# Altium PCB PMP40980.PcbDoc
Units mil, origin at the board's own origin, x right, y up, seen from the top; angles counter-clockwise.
Board outline 2165.35 x 1771.65 mil, 2 copper layers (Top Layer, Bottom Layer), stack 62 mil thick; 58 components, 31 nets, 133 pads, 24 vias.
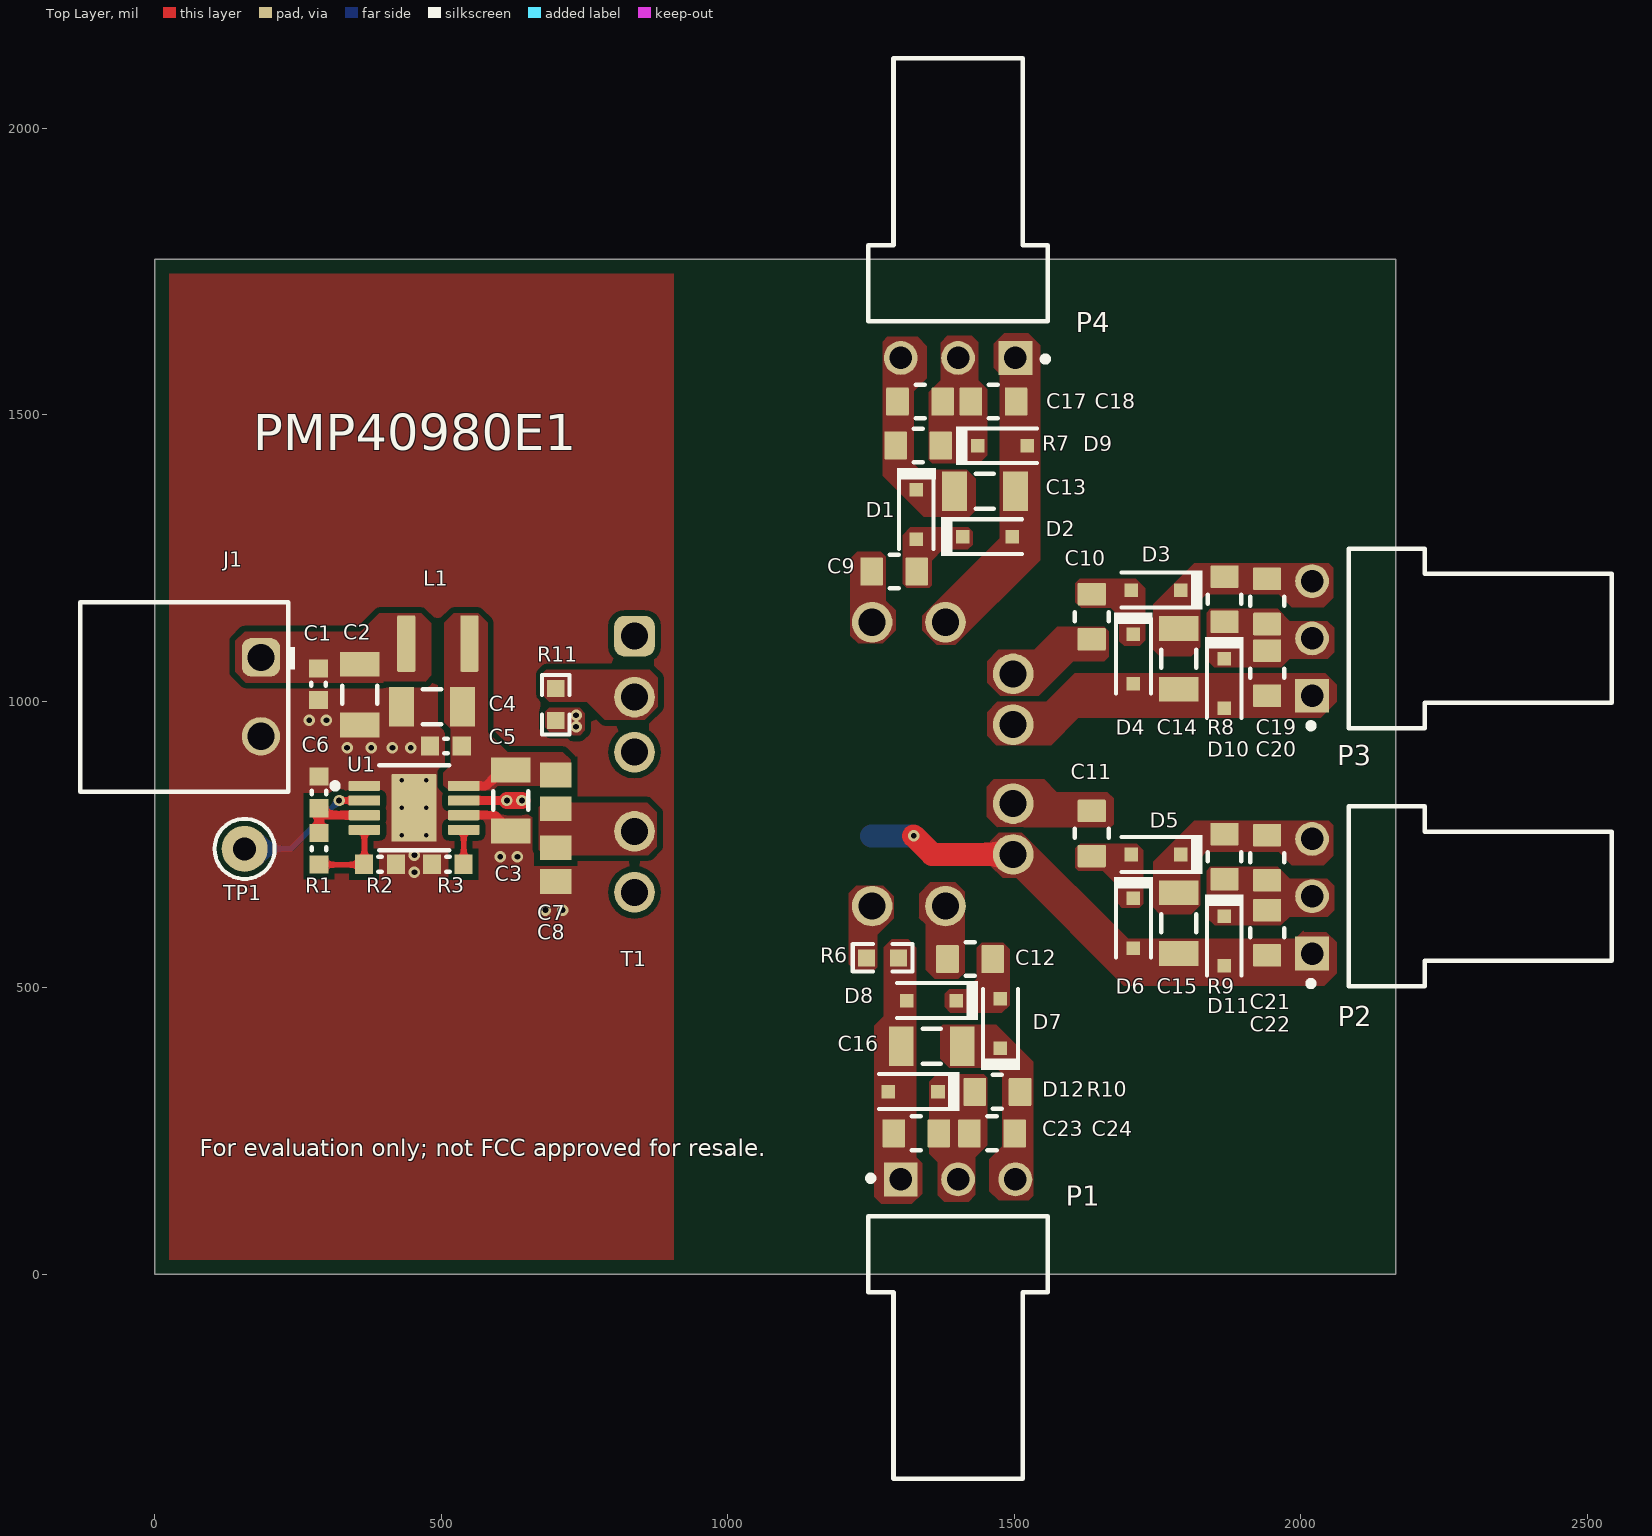
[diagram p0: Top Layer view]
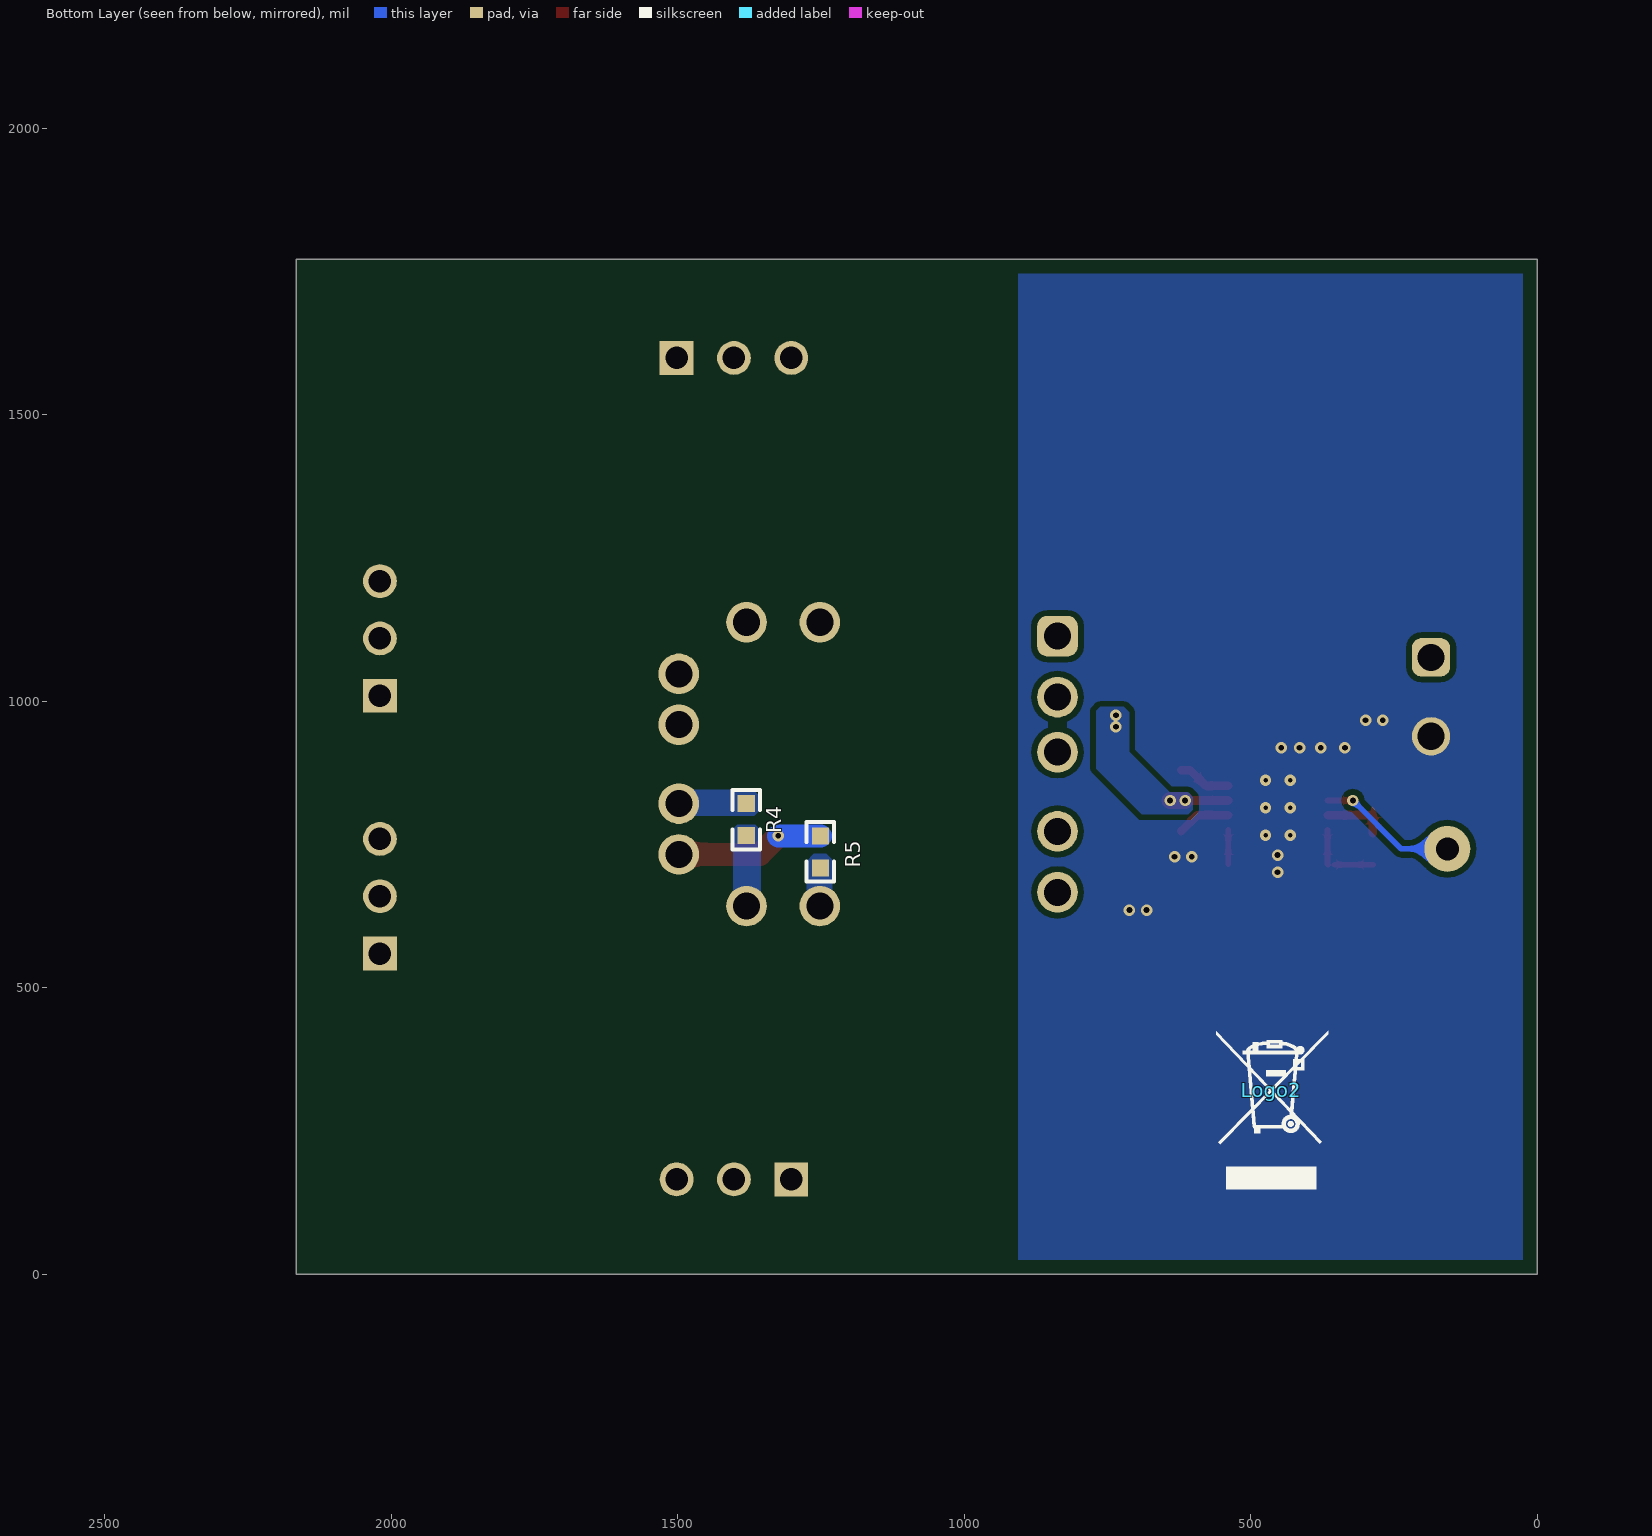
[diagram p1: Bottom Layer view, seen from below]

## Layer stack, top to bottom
Top Solder: solder mask 0.4, Solder Resist, Dk 3.5
Top Layer: signal copper 1.4
Dielectric1: core 59.2, FR-4 High Tg, Dk 4.8
Bottom Layer: signal copper 1.4
Bottom Solder: solder mask 0.4, Solder Resist, Dk 3.5

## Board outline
0,0 0,1771.65 2165.35,1771.65 2165.35,0

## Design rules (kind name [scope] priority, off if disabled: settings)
AcuteAngle [All] p1: minimum=4.50000000000000E+0001 checktracksonly=FALSE
AssemblyTestPointUsage [All] p1: valid=2
BoardOutlineClearance BoardOutlineClearance_MountingHoles [OnCopper and InComponentClass('Mounting Holes')] p1: gap=39.37 ignorepadtopadclearanceinfootprint=FALSE
BoardOutlineClearance BoardOutlineClearance_Poly [OnCopper and IsPoly] p2: gap=25 ignorepadtopadclearanceinfootprint=FALSE
BoardOutlineClearance [OnCopper and Not InComponentClass('Logo') and not InComponentClass('FiducialMark') and not InRegion(1000,500,4000,800) and not InPoly] p3: gap=40 ignorepadtopadclearanceinfootprint=FALSE
Clearance Clearance_Keepouts [((IsTrack Or IsArc) And Not InPoly) And IsFree and IsKeepOut vs ((IsTrack Or IsArc) And Not InPoly) And IsFree and IsKeepOut] p1: gap=0 ignorepadtopadclearanceinfootprint=FALSE
Clearance Clearance_Poly [InPolygon] p2: gap=10 ignorepadtopadclearanceinfootprint=TRUE
Clearance Clearance_FiducialMark [IsKeepOut and InComponentClass('FiducialMark') vs IsPad and InComponentClass('FiducialMark')] p3: gap=0 ignorepadtopadclearanceinfootprint=FALSE
Clearance [All] p4: gap=7.87 ignorepadtopadclearanceinfootprint=TRUE
ComponentClearance ComponentClearance_MountingHoles_FiducialMarks [InComponentClass('Mounting Holes') vs InComponentClass('FiducialMark')] p1: gap=0 collisioncheckmode=3 verticalgap=10 showdistances=FALSE
ComponentClearance ComponentClearance_Shunt [InComponentClass('Header') vs InComponentClass('Shunt')] p2: gap=0 collisioncheckmode=3 verticalgap=0 showdistances=FALSE
ComponentClearance ComponentClearance_Logo [InComponentClass('Logo')] p3: gap=0 collisioncheckmode=3 verticalgap=10 showdistances=FALSE
ComponentClearance ComponentClearance_ScrewToNut [(HasFootprint('NY PMS 440 0025 PH')) vs (HasFootprint('Keystone_1902C'))] p4: gap=0 collisioncheckmode=3 verticalgap=10 showdistances=FALSE
ComponentClearance ComponentClearance_MountingHoles [InComponentClass('Mounting Holes')] p5: gap=0 collisioncheckmode=3 verticalgap=100000 showdistances=FALSE
ComponentClearance ComponentClearance_SmallPassives [HasFootprint('0201*') or HasFootprint('0402*') or HasFootprint('0508') or HasFootprint('0603*') or HasFootprint('0612') or HasFootprint('0805*') or HasFootprint('0815*') or HasFootprint('0830*') or HasFootprint('1206*') or HasFootprint('1210*') or HasFootprint('1808*') or HasFootprint('1812*') or HasFootprint('1825*') or HasFootprint('2010*') or HasFootprint('2220*') or HasFootprint('2225*') or HasFootprint('2512*') or HasFootprint('2728*') or HasFootprint('3518*') vs HasFootprint('0201*') or HasFootprint('0402*') or HasFootprint('0508') or HasFootprint('0603*') or HasFootprint('0612') or HasFootprint('0805*') or HasFootprint('0815*') or HasFootprint('0830*') or HasFootprint('1206*') or HasFootprint('1210*') or HasFootprint('1808*') or HasFootprint('1812*') or HasFootprint('1825*') or HasFootprint('2010*') or HasFootprint('2220*') or HasFootprint('2225*') or HasFootprint('2512*') or HasFootprint('2728*') or HasFootprint('3518*')] p6: gap=5 collisioncheckmode=3 verticalgap=10 showdistances=FALSE
ComponentClearance ComponentClearance_THtoSMT [IsThruComponent vs IsSMTComponent] p7: gap=5 collisioncheckmode=3 verticalgap=30 showdistances=FALSE
ComponentClearance ComponentClearance_THtoTH [IsThruComponent vs IsThruComponent] p8: gap=0 collisioncheckmode=3 verticalgap=30 showdistances=FALSE
ComponentClearance [All] p9: gap=5 collisioncheckmode=3 verticalgap=10 showdistances=FALSE
DiffPairsRouting [All] p1: maxlimit=100 minlimit=10 mostfreqgap=10 toplayer_minwidth=15 toplayer_maxwidth=15 toplayer_prefwidth=15 bottomlayer_minwidth=15 bottomlayer_maxwidth=15 bottomlayer_prefwidth=15 maxuncoupledlength=1000
FabricationTestPointUsage TestPointUsage [All] p1: valid=2 allowmultiple=FALSE
FabricationTestpoint Testpoint [All] p1: side=3 testpointundercomponent=TRUE minsize=40 maxsize=100 preferedsize=60 minholesize=0 maxholesize=40 preferedholesize=32 testpointgrid=1 allowsidetop=TRUE allowsidebottom=TRUE usegrid=TRUE gridtolerance=0.01
FanoutControl Fanout_LCC [IsLCC] p1: bgadir=Out bgaviamode=Centered fanoutstyle=Auto fanoutdirection=Alternating viagrid=1 // Fanout_LCC (Default Rule)
FanoutControl Fanout_BGA [IsBGA] p2: bgadir=Out bgaviamode=Centered fanoutstyle=Auto fanoutdirection=Alternating viagrid=1 // Fanout_BGA (Default Rule)
FanoutControl Fanout_Default [All] p4: bgadir=Out bgaviamode=Centered fanoutstyle=Auto fanoutdirection=Alternating viagrid=1 // Fanout_Default (Default Rule)
FanoutControl Fanout_Small [(CompPinCount < 5)] p5: bgadir=Out bgaviamode=Centered fanoutstyle=Auto fanoutdirection=OutThenIn viagrid=1 // Fanout_Small (Default Rule)
HoleSize [All] p1: absolutevalues=TRUE maxlimit=251 minlimit=7.87 maxpercent=80.000 minpercent=20.000
MinimumAnnularRing MinimumAnnularRing_ThermalPadVias [IsVia and InAnyComponent] p1: minimumring=5.91
MinimumAnnularRing [All] p2: minimumring=7.87
MinimumSolderMaskSliver MinimumSolderMaskSliver_Logo [InComponentClass('Logo') vs InComponentClass('Logo')] p1: minsoldermaskwidth=0.7
MinimumSolderMaskSliver [All] p2: minsoldermaskwidth=3.94
PlaneConnect [All] p1: planeconnectstyle=Relief reliefexpansion=10 reliefentries=4 reliefconductorwidth=10 reliefairgap=10
PolygonConnect [All] p1: connectstyle=Direct reliefconductorwidth=10 reliefentries=4 polygonreliefangle="90 Angle" airgapwidth=10
RoutingVias ThermalPadVias [IsVia and InAnyComponent] p1: holewidth=7.87 width=19.68 viastyle="Through Hole" minholewidth=7.87 minwidth=19.68 maxholewidth=12.99 maxwidth=23.62
RoutingVias [All] p2: holewidth=10 width=10 viastyle="Through Hole" minholewidth=5 minwidth=6 maxholewidth=40 maxwidth=65
SilkToBoardRegionClearance [Not ((IsComment or IsDesignator) And (Hide <> 'False')) and not InRegion(1000,500,4000,800)] p1:
SilkToSilkClearance SilkToSilkClearance_Pb-FreeLogo [(HasFootprint('Pb-Free_Overlay_Medium') OR HasFootprint('Pb-Free_Overlay_Small')) vs (HasFootprint('Pb-Free_Overlay_Medium') OR HasFootprint('Pb-Free_Overlay_Small'))] p1: silktosilkclearance=0
SilkToSilkClearance [All] p2: silktosilkclearance=3.94
SilkToSolderMaskClearance SilkToComponentPadClearance [(IsPad or IsFill or IsRegion) and InAnycomponent] p1: minsilkscreentomaskgap=5 clearancetoexposedcopper=TRUE
SilkToSolderMaskClearance "Silk to Solder Mask Opening" [All] p2: minsilkscreentomaskgap=3.94 clearancetoexposedcopper=FALSE
SolderMaskExpansion [All] p1: expansion=1.97
UnRoutedNet [All] p1: checkbadconnections=TRUE
Width [All] p1: maxlimit=100 minlimit=6 preferedwidth=10 checkconnectedcopper=TRUE
14 further rules are at their usual default settings.

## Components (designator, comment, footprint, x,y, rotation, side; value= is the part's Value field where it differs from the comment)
C1 "CGA3E2X7R1H104K080AA" 0603L 286.01,1029.52 r270 top value=0.1uF
C2 "CGA5L1X7R1H106K160AC" 1206_190L 357.73,1011.52 r270 top value=10uF
C3 "CGA5L1X7R1H106K160AC" 1206_190L 620.97,826.86 r270 top value=10uF
C4 "CGA5L1X7R1H106K160AC" 1206_190L 483.8,990.09 r180 top value=10uF
C5 "CGA3E2X7R1H104K080AA" 0603L 508.16,922.09 r180 top value=0.1uF
C6 "CGA3E1X7R1E105K080AC" 0603L 286.78,840.94 r90 top value=1uF
C7 "GCD21BR71H683KA01L" 0805L 699.8,842.02 r270 top value=0.068uF
C8 "GCD21BR71H683KA01L" 0805L 699.8,714.97 r270 top value=0.068uF
C9 "CGA4J3X7R1H105K125AB" 0805_HV1 1290.22,1226.45 r0 top value=1uF
C10 "CGA4J3X7R1H105K125AB" 0805_HV1 1634.92,1147.63 r90 top value=1uF
C11 "CGA4J3X7R1H105K125AB" 0805_HV1 1634.92,769.36 r270 top value=1uF
C12 "CGA4J3X7R1H105K125AB" 0805_HV1 1422.61,550.23 r0 top value=1uF
C13 "GCM31CR71H225KA55L" 1206_180L 1448.5,1366.52 r0 top value=2.2uF
C14 "GCM31CR71H225KA55L" 1206_180L 1786.8,1074.12 r270 top value=2.2uF
C15 "GCM31CR71H225KA55L" 1206_180L 1786.8,612.93 r270 top value=2.2uF
C16 "GCM31CR71H225KA55L" 1206_180L 1355.73,398.38 r180 top value=2.2uF
C17 "CGA4J3X7R1H225K125AE" 0805_HV1 1335.37,1523 r0 top value=2.2uF
C18 "GCM21BR71A225KA37L" 0805_HV1 1463.5,1523 r0 top value=2.2uF
C19 "CGA4J3X7R1H225K125AE" 0805_HV1 1941,1174.18 r270 top value=2.2uF
C20 "GCM21BR71A225KA37L" 0805_HV1 1941,1049.06 r270 top value=2.2uF
C21 "CGA4J3X7R1H225K125AE" 0805_HV1 1941,727 r270 top value=2.2uF
C22 "GCM21BR71A225KA37L" 0805_HV1 1941,596 r270 top value=2.2uF
C23 "CGA4J3X7R1H225K125AE" 0805_HV1 1460.94,246 r180 top value=2.2uF
C24 "GCM21BR71A225KA37L" 0805_HV1 1328.77,246 r180 top value=2.2uF
D1 "BAT165E6327HTSA1" SOD-323 1328.77,1325.88 r270 top value=40V
D2 "BAT165E6327HTSA1" SOD-323 1453.25,1287.15 r0 top value=40V
D3 "BAT165E6327HTSA1" SOD-323 1747.23,1193.84 r180 top value=40V
D4 "BAT165E6327HTSA1" SOD-323 1707.43,1073.82 r270 top value=40V
D5 "BAT165E6327HTSA1" SOD-323 1747.23,732.65 r180 top value=40V
D6 "BAT165E6327HTSA1" SOD-323 1707.44,612.64 r270 top value=40V
D7 "BAT165E6327HTSA1" SOD-323 1475.45,437.91 r90 top value=40V
D8 "BAT165E6327HTSA1" SOD-323 1355.42,477.75 r180 top value=40V
D9 "MMSZ5223BS-7-F" SOD-323 1479.19,1445.88 r0 top value=2.7V
D10 "MMSZ5223BS-7-F" SOD-323 1866.17,1031 r270 top value=2.7V
D11 "MMSZ5223BS-7-F" SOD-323 1866.18,581.9 r270 top value=2.7V
D12 "MMSZ5223BS-7-F" SOD-323 1323.42,319.02 r180 top value=2.7V
J1 "1844210" Phoenix_1844210 185.31,1007.86 r270 top
L1 "TFM322512ALMA1R0MTAA" TFM322512 494,1100.65 r0 top value=1uH
Logo1 "FCC disclaimer" FCC_disclaimer 1986.54,3281.57 r0 top
Logo2 "WEEE logo" WEEE_Minimum 464.31,321 r180 bottom
P1 "61900311021" 61900311021 1401.65,-127.5 r0 top
P2 "61900311021" 61900311021 2312.66,659.83 r90 top
P3 "61900311021" 61900311021 2312.66,1109.64 r90 top
P4 "61900311021" 61900311021 1401.65,1892.38 r180 top
R1 "CRCW06033K32FKEA" 0603L 286.78,742.51 r90 top value=3.32k
R2 "CRCW060310K2FKEA" 0603L 393.07,715.64 r180 top value=10.2k
R3 "ERJ-3EKF4022V" 0603L 511.55,715.64 r0 top value=40.2k
R4 "CRCW06030000Z0EA" 0603_HV 1380.25,793.57 r90 bottom value=0
R5 "CRCW06030000Z0EA" 0603_HV 1250.86,737.14 r90 bottom value=0
R6 "CRCW06030000Z0EA" 0603_HV 1269.94,552.19 r180 top value=0
R7 "ERJ-6GEYJ512V" 0805_HV1 1332.15,1446.43 r180 top value=5.1k
R8 "ERJ-6GEYJ512V" 0805_HV1 1866.71,1178.04 r90 top value=5.1k
R9 "ERJ-6GEYJ512V" 0805_HV1 1866.71,728.93 r90 top value=5.1k
R10 "ERJ-6GEYJ512V" 0805_HV1 1470.45,318.45 r0 top value=5.1k
R11 "CRCW06030000Z0EA" 0603_HV 699.8,994.28 r90 top value=0
T1 "750345026" Wurth_EPW15_13 1167.49,890.34 r0 top
TP1 "5001" Keystone5001 156.8,742.51 r90 top
U1 "UCC25800DGNRQ1" DGN0008G-MFG 452.5,814.07 r0 top

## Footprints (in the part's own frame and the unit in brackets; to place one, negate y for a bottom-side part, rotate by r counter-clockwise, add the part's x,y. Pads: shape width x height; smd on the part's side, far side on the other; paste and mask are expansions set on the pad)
0603_HV [mil] "Ernesto recommended land pattern.  26 mil between pads."
  rect 30x30 smd: 1(-28,0) 2(28,0)
  silkscreen extent -52,-24 52,24, body extent -34,-19 34,19, height 39
0603L [mm] "0603 from SM-752 data"
  rect 0.8x0.85 smd: 1(-0.7,0) 2(0.7,0)
  silkscreen extent -0.07,-0.33 0.07,0.33, body extent -0.87,-0.47 0.87,0.47, height 1
0805_HV1 [mm] "Custom footprint based on analyzing multiple manufacturer recommendations"
  rrect10% 1x1.25 smd: 1(-1,0) 2(1,0)
  silkscreen extent -0.2,-0.75 0.2,0.75, body extent -1.1,-0.72 1.1,0.73, height 1.45
0805L [mm] "0805 from SM-752 data"
  rect 1.1x1.4 smd: 1(-0.75,0) 2(0.75,0)
  body extent -1.1,-0.72 1.1,0.72, height 1.45
1206_180L [mm] "1206_180"
  rect 1.1x1.75 smd: 1(-1.35,0) 2(1.35,0)
  silkscreen extent -0.4,-0.77 0.4,0.77, body extent -1.75,-0.95 1.75,0.95, height 1.8
1206_190L [mm] "1206_190"
  rect 1.1x1.75 smd: 1(-1.35,0) 2(1.35,0)
  silkscreen extent -0.4,-0.77 0.4,0.77, body extent -1.75,-0.95 1.75,0.95, height 1.9
61900311021 [mm] "2.54mm Male Left Angled Header Bottom Locking, 3p"
  rect 1.5x1.5 hole 1: 1(-2.54,7.45)
  round 1.5 hole 1: 2(0,7.45) 3(2.54,7.45)
  silkscreen extent -3.99,-5.82 3.98,7.62, body extent -3.81,-5.75 3.81,7.77, height 5.83
DGN0008G-MFG [mm]
  rrect22% 1.4x0.45 smd paste+0 mask+0: 1(-2.2,0.975) 2(-2.2,0.325) 3(-2.2,-0.325) 4(-2.2,-0.975) 5(2.2,-0.975) 6(2.2,-0.325) 7(2.2,0.325) 8(2.2,0.975)
  rrect5% 2x3 smd paste-1000 mask-1000: 9(0,0)
  silkscreen extent -3.62,-1.88 1.55,1.88, body extent -3,-1.8 3,1.8, height 0.25
FCC_disclaimer [mil]
Keystone5001 [mil] "For Keystone 500x miniature loop terminals"
  round 80 hole 40: 1(0,0)
  silkscreen extent -52,-52 52,52, body extent -49,-49 49,49, height 182
Phoenix_1844210 [mm] "Header, 3.5mm, 2x1, R/A, TH"
  rrect50% 1.7x1.7 hole 1.2: 1(-1.75,0)
  round 1.7 hole 1.2: 2(1.75,0)
  silkscreen extent -4.2,-8 4.2,1.5, body extent -4.2,-8 4.2,1.2, height 7.75
SOD-323 [mm] "NXP recommended land pattern"
  rect 0.6x0.6 smd paste-0.05: 1(-1.1,0) 2(1.1,0)
  silkscreen extent -2.06,-0.86 1.53,0.86, body extent -1.3,-0.67 1.3,0.68, height 1.1
TFM322512 [mm] "TDK inductor"
  rrect13% 0.8x2.5 smd: 1(-1.4,0) 2(1.4,0)
  body extent -1.7,-1.35 1.7,1.35, height 1.2
WEEE_Minimum [mil] "WEEElie bin"
  silkscreen extent -95,-172 99,104
Wurth_EPW15_13 [mm] "TH, 13-Leads, Body 22.1x15.7mm"
  rrect50% 1.8x1.8 hole 1.2: 1(-8.39,5.67)
  round 1.8 hole 1.2: 2(-8.39,2.97) 3(-8.39,0.53) 4(-8.39,-2.98) 5(-8.39,-5.68) 6(2.14,-6.29) 7(2.14,6.29) 8(5.39,6.29) 11(5.39,-6.29) 12(8.39,-4) 13(8.39,-1.75) 14(8.39,1.75) 15(8.39,4)
  body extent -10.9,-7.5 10.4,7.52, height 22.6

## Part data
C1 C5: library part CMP-0007078-3, "CAP, CERM, 0.1 uF, 50 V, +/- 10%, X7R, AEC-Q200 Grade 1, 0603", Cap_Case=0603, Manufacturer=TDK, Supplier Part Number 1=445-5666-1-ND, TempCo=X7R, Tolerance_%=10%, Value1="0.0296 ohm", Value2=50V, ValueDisplayed=0.1uF
C2 C3 C4: library part CMP-0085950-1, "CAP, CERM, 10 µF, 50 V,+/- 10%, X7R, AEC-Q200 Grade 1, 1206", Cap_Case=1206, Manufacturer=TDK, TempCo=X7R, Tolerance_%=10%, Value2=50V, ValueDisplayed=10µF
C6: library part CMP-0076705-3, "CAP, CERM, 1 µF, 25 V,+/- 10%, X7R, AEC-Q200 Grade 1, 0603", Cap_Case=1.6x0.8x0.8mm, Manufacturer=TDK, Supplier Part Number 1=445-6931-1-ND, TempCo=X7R, Tolerance_%=10%, Value2=25V, ValueDisplayed=1µF
C7 C8: library part CMP-0008359-1, "CAP, CERM, 0.068 uF, 50 V, +/- 10%, X7R, 0805", Cap_Case=0805, Manufacturer=MuRata, Supplier Part Number 1=490-1663-1-ND, TempCo=X7R, Tolerance_%=10%, Value1=Unknown, Value2=50V, ValueDisplayed=0.068uF
C9 C10 C11 C12: library part CMP-0007976-2, "CAP, CERM, 1 uF, 50 V, +/- 10%, X7R, AEC-Q200 Grade 1, 0805", Cap_Case=0805, Manufacturer=TDK, Supplier Part Number 1=445-6961-1-ND, TempCo=X7R, Tolerance_%=10%, Value1="0.008782 ohm", Value2=50V, ValueDisplayed=1uF
C13 C14 C15 C16: library part CMP-0008814-1, "CAP, CERM, 2.2 uF, 50 V, +/- 10%, X7R, AEC-Q200 Grade 1, 1206", Cap_Case=1206, Manufacturer=MuRata, Supplier Part Number 1=490-4796-1-ND, TempCo=X7R, Tolerance_%=10%, Value1=Unknown, Value2=50V, ValueDisplayed=2.2uF
C17 C19 C21 C23: library part CMP-0860897-1, "CAP, CERM, 2.2 µF, 50 V,+/- 10%, X7R, AEC-Q200 Grade 1, 0805", Cap_Case=0805, Manufacturer=TDK, TempCo=X7R, Tolerance_%=10%, Value2=50V, ValueDisplayed=2.2µF
C18 C20 C22 C24: library part CMP-0008317-1, "CAP, CERM, 2.2 uF, 10 V, +/- 10%, X7R, 0805", Cap_Case=0805, Manufacturer=MuRata, Supplier Part Number 1=490-1696-1-ND, TempCo=X7R, Tolerance_%=10%, Value1="0.006 ohm", Value2=10V, ValueDisplayed=2.2uF
D1 D2 D3 D4 D5 D6 D7 D8: library part CMP-0028882-1, "Diode, Schottky, 40 V, 0.75 A, AEC-Q101, SOD-323", Manufacturer="Infineon Technologies", Supplier Part Number 1=BAT165E6327HTSA1CT-ND, Value1=0.75A, Value2=0.74V
D9 D10 D11 D12: library part CMP-0005847-3, "Diode, Zener, 2.7 V, 200 mW, SOD-323", Manufacturer="Diodes Inc.", Power_W=200mW, Value1=0.2W
J1: library part CMP-0055556-1, "Header(shrouded), 3.5mm, 2x1, Tin, TH", Color=Green, Current_A=8A, Manufacturer="Phoenix Contact", Supplier Part Number 1=277-2416-ND, Voltage_V=160V
L1: library part CMP-0085828-1, "Inductor, Thin Film, 1 µH, 4 A, 0.037 ohm, AEC-Q200 Grade 0, SMD", Manufacturer=TDK, Value1="0.037 ohm", Value2=4A, ValueDisplayed=1µH
Logo1: library part CMP-0074847-1, "FCC_disclaimer"
Logo2: library part CMP-0074769-1
P1 P2 P3 P4: "WR-WTB THT Male Left Angled Bottom Locking Header, pitch 2.54mm, 3p", Contact Resistance=20mOhm, Operating Temperature="-40 to +105degC", Rated Current=3A, Withstanding Voltage=1000VAC, Working Voltage=250VAC
R1: library part CMP-0022375-4, "RES, 3.32 k, 1%, 0.1 W, AEC-Q200 Grade 0, 0603", Manufacturer=Vishay-Dale, Power_W=100mW, Supplier Part Number 1=541-3.32KHCT-ND, TempCo="100 ppm/C", Tolerance_%=1%, Value2=0.1W, Value_Code=3k32, ValueDisplayed=3.32k
R2: library part CMP-0021999-4, "RES, 10.2 k, 1%, 0.1 W, AEC-Q200 Grade 0, 0603", Manufacturer=Vishay-Dale, Power_W=100mW, Supplier Part Number 1=541-10.2KHCT-ND, TempCo="100 ppm/C", Tolerance_%=1%, Value2=0.1W, Value_Code=10k2, ValueDisplayed=10.2k
R3: library part CMP-0022700-1, "RES, 40.2 k, 1%, 0.1 W, AEC-Q200 Grade 0, 0603", Manufacturer=Panasonic, Power_W=100mW, Supplier Part Number 1=P40.2KHDKR-ND, TempCo="100 ppm/C", Tolerance_%=1%, Value2=0.1W, Value_Code=40k2, ValueDisplayed=40.2k
R4 R5 R6 R11: library part CMP-0025697-4, "RES, 0, 5%, 0.1 W, AEC-Q200 Grade 0, 0603", Manufacturer=Vishay-Dale, Power_W=100mW, Supplier Part Number 1=541-0.0GCT-ND, TempCo="200 ppm/C", Tolerance_%=5%, Value2=0.1W, Value_Code=0000, ValueDisplayed=0
R7 R8 R9 R10: library part CMP-0020740-3, "RES, 5.1 k, 5%, 0.125 W, AEC-Q200 Grade 0, 0805", Manufacturer=Panasonic, Power_W=125mW, Supplier Part Number 1=P5.1KACT-ND, TempCo="200 ppm/C", Tolerance_%=5%, Value2=0.125W, Value_Code=5k10, ValueDisplayed=5.1k
T1: library part XFMR3, Manufacturer=Wurth
TP1: library part CMP-0055138-1, "Test Point, Miniature, Black, TH", Color=Black, Manufacturer=Keystone, Supplier Part Number 1=36-5001-ND
U1: library part CMP-0088494-2, "Open Loop LLC Transformer Driver for Isolated Bias Supplies", Manufacturer="Texas Instruments", Max Supply Voltage=36V, Min Supply Voltage=12V, Nominal Supply Current=500uA, Operating Temperature Range="-40°C to +150°C", Switching Frequency=100-2000kHz

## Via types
v1: diameter 20, hole 10, Top Layer to Bottom Layer, tented both sides, 18 vias
v2: diameter 19.68, hole 7.87, Top Layer to Bottom Layer, tented both sides, 6 vias

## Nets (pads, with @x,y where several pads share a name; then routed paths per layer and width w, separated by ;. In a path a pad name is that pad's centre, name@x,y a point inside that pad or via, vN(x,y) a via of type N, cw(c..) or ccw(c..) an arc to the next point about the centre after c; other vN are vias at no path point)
FLT: TP1.1 U1.2 | length 244
  Top Layer w10: v1(321.66,826.86) U1.2
  Bottom Layer w10: TP1.1 237.31,742.51 v1(321.66,826.86)
GND: C1.2 C2.2 C3.2 C4.2 C5.2 C6.2 C8.2 J1.2 R2.1 R3.1 U1.1 U1.6 U1.9 | length 93.3
  Top Layer w15: U1.6 593.42,801.27 C3.2
  other v1: 681.66,635.65 711.66,635.65 453.06,701.65 602.86,728.86 632.86,728.86 453.06,731.65 335.61,919.09 377.66,919.09 414.73,919.09 446.66,919.09 269.66,967.11 299.66,967.11
  other v2: 430.85,766.04 474.15,766.04 430.85,814.07 474.15,814.07 430.85,862.1 474.15,862.1
NetC1_1: C1.1 C2.1 J1.1 L1.1
NetC7_2: C7.2 C8.1 T1.4
NetC9_1: C9.1 T1.7
NetC9_2: C9.2 D1.2 D2.1
NetC10_1: C10.1 T1.15
NetC10_2: C10.2 D3.2 D4.1
NetC11_1: C11.1 R4.2 T1.13
NetC11_2: C11.2 D5.2 D6.1
NetC12_1: C12.1 R4.1 T1.11
NetC12_2: C12.2 D7.2 D8.1
NetR5_1: R5.1 R6.2 T1.6
NetR11_2: R11.2 T1.2
OC_DT: R1.1 R2.2 U1.4 | length 128.2
  Top Layer w10: R1.1 R2.2@353.82,714.95 ; R2.2@364.82,714.95 R2.2 365.89,716.01 U1.4
PFC_H_G1_GND: C21.2 C22.1 D11.1 P2.2 R9.1
PFC_H_G1_N: C15.2 C22.2 D6.2 D11.2 P2.1 R5.2 T1.12 | length 260.3
  Top Layer w40: v1(1324.27,765.15) 1356.57,732.86 T1.12
  Bottom Layer w40: R5.2 v1@1324.26,765.14
PFC_H_G1_P: C15.1 C21.1 D5.1 P2.3 R9.2
PFC_H_G2_GND: C19.2 C20.1 D10.1 P3.2 R8.1
PFC_H_G2_N: C14.2 C20.2 D4.2 D10.2 P3.1 T1.14
PFC_H_G2_P: C14.1 C19.1 D3.1 P3.3 R8.2
PFC_H_G3_GND: C17.2 C18.1 D9.1 P4.2 R7.1
PFC_H_G3_N: C13.2 C18.2 D2.2 D9.2 P4.1 T1.8
PFC_H_G3_P: C13.1 C17.1 D1.1 P4.3 R7.2
PFC_L_G_GND: C23.2 C24.1 D12.1 P1.2 R10.1
PFC_L_G_N: C16.2 C24.2 D8.2 D12.2 P1.1 R6.1
PFC_L_G_P: C16.1 C23.1 D7.1 P1.3 R10.2
RT: R3.2 U1.5 | length 60
  Top Layer w10: R3.2 U1.5
SW: R11.1 U1.7 | length 101.5
  Top Layer w15: U1.7 v1(614.46,826.86)
  Top Layer w30: v1(614.46,826.86) v1(640.66,826.86)
  other v1: 735.22,955.47 735.22,975.67
VCC: C3.1 C4.1 C5.1 C7.1 L1.2 U1.8 | length 93.3
  Top Layer w15: U1.8 578.48,852.45 606.04,880.01 C3.1
VREG: C6.1 R1.2 U1.3 | length 122.4
  Top Layer w6: C6.1@286.78,801.27 C6.1
  Top Layer w15: R1.2 286.78,801.27 U1.3
pads on no net: T1.1 T1.3 T1.5

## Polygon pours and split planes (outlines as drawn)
SW on Top Layer "TOP_LAYER_SW_P300" (solid, remove dead copper, pour order 300): 685.28,946.05 724,946.05 729.26,940.79 742.4,940.79 750.74,949.13 750.74,979.35 741.45,988.64 687.67,988.64 681.15,982.41 681.08,950.25
NetR11_2 on Top Layer "TOP_LAYER_NETR11_2_P298" (solid, remove dead copper, pour order 298): 683.43,1055.11 676.18,1047.85 676.18,1011.28 688.11,998.84 731.44,998.84 754.15,998.84 785.4,967.58 854.94,967.58 878,990.64 878,1041 863.89,1055.11
GND on Top Layer "TOP_LAYER_GND_P302" (solid, remove dead copper, pour order 302): 0,1771.65 905.51,1771.65 905.51,0 0,0
PFC_H_G3_N on Top Layer "TOP_LAYER_PFC_H_G3_N_P268" (solid, remove dead copper, pour order 268): 1474.36,1300.57 1474.36,1284.81 1339.24,1149.69 1339.24,1123.66 1364.32,1098.57 1397.1,1098.57 1544.94,1246.42 1544.94,1620.94 1524,1641.88 1482.25,1641.88 1464.25,1623.88 1464.25,1585.88 1462.25,1583.88 1474.36,1571.77
NetC9_2 on Top Layer "TOP_LAYER_NETC9_2_P266" (solid, remove dead copper, pour order 266): 1318.69,1303.57 1421.31,1303.57 1426.94,1297.94 1426.94,1273.54 1418.4,1265 1375.25,1265 1355.73,1245.48 1355.73,1202.32 1351.31,1197.91 1311.61,1197.91 1304.87,1204.65 1305.04,1289.93
NetC9_1 on Top Layer "TOP_LAYER_NETC9_1_P264" (solid, remove dead copper, pour order 264): 1275.94,1175.5 1275.94,1251.92 1266.94,1260.92 1226.14,1260.92 1213.94,1248.73 1213.94,1176.57 1213.94,1114.67 1227.11,1101.5 1269.94,1101.5 1292.8,1124.35 1292.8,1158.64
NetR5_1 on Top Layer "TOP_LAYER_NETR5_1_P262" (solid, remove dead copper, pour order 262): 1271.42,678.57 1289.8,660.2 1289.8,621.43 1260.94,592.57 1260.94,536.19 1253.94,529.19 1218.94,529.19 1218.94,533.59 1210.94,541.59 1210.94,665.41 1224.11,678.57
NetC12_1 on Top Layer "TOP_LAYER_NETC12_1_P260" (solid, remove dead copper, pour order 260): 1396.51,683.95 1412.94,667.51 1412.94,526.57 1402.14,515.77 1360.75,515.77 1344.94,531.57 1344.94,611.16 1333.53,622.57 1333.94,622.99 1333.94,664.57 1353.32,683.95
NetC11_1 on Top Layer "TOP_LAYER_NETC11_1_P258" (solid, remove dead copper, pour order 258): 1464.27,863.57 1551.94,863.57 1573.94,841.57 1662.22,841.57 1672.94,830.85 1672.94,785.74 1664.45,777.24 1661.11,780.57 1469.94,780.57 1451.94,798.57 1451.94,851.25
NetC10_1 on Top Layer "TOP_LAYER_NETC10_1_P256" (solid, remove dead copper, pour order 256): 1659.68,1129.78 1664.96,1124.5 1664.96,1075.04 1659.57,1069.65 1602.33,1069.65 1542.31,1009.64 1475.08,1009.64 1452.25,1032.48 1452.25,1069.89 1472.23,1089.87 1534.87,1089.87 1574.78,1129.78
NetC1_1 on Top Layer "TOP_LAYER_NETC1_1_P240" (solid, remove dead copper, pour order 240): 156.66,1121.65 359.8,1121.65 391.95,1153.8 465.11,1153.8 482.8,1136.11 482.8,1045.02 470.43,1032.65 159.12,1032.65 140.66,1051.11 140.66,1105.65
VCC on Top Layer "TOP_LAYER_VCC_P238" (solid, remove dead copper, pour order 238): 504.8,963.84 504.8,1136.8 521.78,1153.78 564.48,1153.78 580.8,1137.46 580.8,945.65 620.97,905.48 620.97,870.09 529.37,870.09 516.8,882.65 516.8,951.84
NetC7_2 on Top Layer "TOP_LAYER_NETC7_2_P234" (solid, remove dead copper, pour order 234): 674.68,823.08 859.44,823.07 875.94,806.57 875.94,746.11 861.45,731.62 679.29,731.62 669.8,741.11 669.8,818.2
NetC12_2 on Top Layer "TOP_LAYER_NETC12_2_P198" (solid, remove dead copper, pour order 198): 1415.96,497.79 1433.94,515.77 1433.94,569.77 1442.96,578.78 1480.5,578.78 1491.94,567.33 1491.94,469.57 1477.94,456.77 1388.24,456.77 1378.24,466.77 1378.24,493.77 1382.26,497.79
NetC11_2 on Top Layer "TOP_LAYER_NETC11_2_P194" (solid, remove dead copper, pour order 194): 1680.87,646.4 1687.73,639.53 1718.33,639.53 1724.94,646.15 1724.94,740 1713.11,751.83 1610.83,751.83 1606.38,747.38 1606.38,709.14 1611.52,704 1653.86,704 1680.87,677
NetC10_2 on Top Layer "TOP_LAYER_NETC10_2_P192" (solid, remove dead copper, pour order 192): 1683.37,1104.63 1691.37,1096.63 1718.37,1096.63 1728.37,1106.63 1728.37,1196.88 1711.54,1213.71 1614.04,1213.71 1606.37,1206.03 1606.37,1172.91 1616.43,1162.84 1668.17,1162.84 1683.37,1147.63
PFC_H_G2_P on Top Layer "TOP_LAYER_PFC_H_G2_P_P184" (solid, remove dead copper, pour order 184): 1813.76,1241.04 2051.17,1241.04 2056.17,1236.04 2056.17,1180.36 2039.85,1164.04 1984.17,1164.04 1961.19,1187.02 1835.14,1187.02 1824.17,1176.04 1824.19,1094.07 1808.66,1078.54 1753.74,1078.54 1742.23,1090.04 1742.23,1169.51
PFC_H_G2_GND on Top Layer "TOP_LAYER_PFC_H_G2_GND_P182" (solid, remove dead copper, pour order 182): 1842.17,1161.04 1959.66,1161.04 1980.67,1140.04 2046.17,1140.04 2058.17,1128.04 2058.17,1085.54 2046.67,1074.04 1980.17,1074.04 1965.17,1059.04 1849.17,1059.04 1835.67,1072.54 1835.67,1154.55
PFC_H_G2_N on Top Layer "TOP_LAYER_PFC_H_G2_N_P180" (solid, remove dead copper, pour order 180): 1605.41,1049.04 1555.21,998.84 1470.47,998.84 1452.25,980.62 1452.25,939.63 1468.22,923.66 1564.47,923.66 1611.77,970.96 2034.28,970.96 2062.17,998.84 2062.17,1029.04 2042.17,1049.04 2004.17,1049.04
PFC_L_G_P on Top Layer "TOP_LAYER_PFC_L_G_P_P178" (solid, remove dead copper, pour order 178): 1533.06,371.4 1533.06,134 1528.06,129 1472.37,129 1456.06,145.31 1456.06,201 1479.03,223.97 1479.03,350.02 1468.06,361 1386.08,360.97 1370.55,376.5 1370.55,431.42 1374.89,435.76 1468.7,435.76
PFC_L_G_GND on Top Layer "TOP_LAYER_PFC_L_G_GND_P176" (solid, remove dead copper, pour order 176): 1453.06,343 1453.06,225.5 1432.06,204.5 1432.06,139 1420.06,127 1377.56,127 1366.06,138.5 1366.06,195.93 1351.06,210.93 1351.06,336 1364.55,349.49 1446.56,349.49
PFC_L_G_N on Top Layer "TOP_LAYER_PFC_L_G_N_P174" (solid, remove dead copper, pour order 174): 1328.94,570.39 1314.76,584.57 1285.76,584.57 1272.03,570.53 1272.03,450.66 1255.06,433.69 1255.06,135.5 1267.56,123 1321.06,123 1339.06,141 1339.06,193.94 1328.94,204.05
PFC_H_G1_P on Top Layer "TOP_LAYER_PFC_H_G1_P_P172" (solid, remove dead copper, pour order 172): 1813.76,791.24 2051.17,791.24 2056.17,786.24 2056.17,730.55 2039.85,714.24 1984.17,714.24 1961.19,737.21 1835.14,737.21 1824.17,726.24 1824.19,644.26 1808.66,628.73 1753.74,628.73 1742.23,640.24 1742.23,719.71
PFC_H_G1_GND on Top Layer "TOP_LAYER_PFC_H_G1_GND_P170" (solid, remove dead copper, pour order 170): 1842.17,711.24 1959.66,711.24 1980.67,690.24 2046.17,690.24 2058.17,678.24 2058.17,635.74 2046.67,624.24 1980.17,624.24 1965.17,609.24 1849.17,609.24 1835.67,622.73 1835.67,704.75
PFC_H_G1_N on Top Layer "TOP_LAYER_PFC_H_G1_N_P168" (solid, remove dead copper, pour order 168): 1479.8,691.67 1503.18,691.67 1691.01,503.83 2040.26,503.83 2062.17,525.74 2062.17,579.24 2044.17,597.24 2006.17,597.24 2004.17,599.24 1990.17,585.24 1698.92,585.24 1513.16,771 1473,771 1458.11,756.11 1458.11,713.36
PFC_H_G3_GND on Top Layer "TOP_LAYER_PFC_H_G3_GND_P164" (solid, remove dead copper, pour order 164): 1350.25,1421.88 1350.25,1539.38 1371.25,1560.38 1371.25,1625.88 1383.25,1637.88 1425.75,1637.88 1437.25,1626.38 1437.25,1559.88 1452.25,1544.88 1452.25,1428.88 1438.75,1415.39 1356.74,1415.39
PFC_H_G3_P on Top Layer "TOP_LAYER_PFC_H_G3_P_P162" (solid, remove dead copper, pour order 162): 1270.25,1393.48 1270.25,1627.66 1278.47,1635.88 1330.93,1635.88 1347.25,1619.57 1347.25,1563.88 1324.27,1540.91 1324.27,1414.86 1335.25,1403.88 1417.22,1403.91 1432.75,1388.37 1432.75,1333.45 1421.25,1321.94 1341.78,1321.94
no net on Top Layer "TOP_LAYER_NONET_P150" (solid, remove dead copper, pour order 150): 1662.45,659.5
no net on Top Layer "TOP_LAYER_NONET_P142" (solid, remove dead copper, pour order 142): 470.98,902.42
VCC on Top Layer "TOP_LAYER_VCC_P118" (solid, remove dead copper, pour order 118): 712.06,911.4 565.39,911.4 539.97,911.4 503.66,875.09 503.66,853.86 512.66,844.86 590.46,844.86 598.33,852.73 715.46,852.73 725.51,861.8 725.51,897.95
no net on Top Layer "TOP_LAYER_NONET_P090" (solid, remove dead copper, pour order 90): 1614.04,833.95
no net on Bottom Layer "BOTTOM_LAYER_NONET_P296" (solid, remove dead copper, pour order 296): 681,1038
SW on Bottom Layer "BOTTOM_LAYER_SW_P292" (solid, remove dead copper, pour order 292): 721.19,990.09 712.29,981.2 712.29,911.64 641.6,840.94 605.94,840.94 601.29,836.29 601.29,810.73 608.87,803.15 690.26,803.15 769.39,882.28 769.39,983.59 762.9,990.09
GND on Bottom Layer "BOTTOM_LAYER_GND_P304" (solid, remove dead copper, pour order 304): 0,1771.65 905.51,1771.65 905.51,0 0,0
no net on Bottom Layer "BOTTOM_LAYER_NONET_P282" (solid, remove dead copper, pour order 282): 1227.24,789.31
NetR5_1 on Bottom Layer "BOTTOM_LAYER_NETR5_1_P276" (solid, remove dead copper, pour order 276): 1229.86,622.99 1239.28,613.57 1259.94,613.57 1275.03,628.66 1275.03,647.85 1275.03,721.14 1262.56,733.61 1240.38,733.61 1229.86,723.09
NetC11_1 on Bottom Layer "BOTTOM_LAYER_NETC11_1_P274" (solid, remove dead copper, pour order 274): 1368.2,845.74 1514.78,845.74 1525.94,834.57 1525.94,811.57 1514.94,800.57 1366.25,800.57 1355.73,811.09 1355.73,833.27
NetC12_1 on Bottom Layer "BOTTOM_LAYER_NETC12_1_P272" (solid, remove dead copper, pour order 272): 1364.25,784.57 1396.25,784.57 1402.94,777.88 1402.94,628.57 1387.94,613.57 1366.61,613.57 1354.94,625.24 1354.94,775.27
no net on Bottom Layer "BOTTOM_LAYER_NONET_P134" (solid, remove dead copper, pour order 134): 1614.54,638.57

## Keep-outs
Keep-Out Layer:
  text ".Layer_Name" at 233.22,-976.6 h60

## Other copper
Top Layer:
  text ".Layer_Name" at 233.22,-976.6 h60
Bottom Layer:
  text ".Layer_Name" at 233.22,-976.6 h60

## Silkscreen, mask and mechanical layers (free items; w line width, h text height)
Top Overlay:
  text "PMP40980E1" at 171.8,1417.32 h108.27
  text ".Layer_Name" at 233.22,-976.6 h60
Bottom Overlay:
  text ".Layer_Name" at 233.22,-976.6 h60
Top Paste:
  text ".Layer_Name" at 233.22,-976.6 h60
Bottom Paste:
  text ".Layer_Name" at 233.22,-976.6 h60
Top Solder:
  text ".Layer_Name" at 233.22,-976.6 h60
  text ".Layer_Name" at 233.22,-976.6 h60
Bottom Solder:
  text ".Layer_Name" at 233.22,-976.6 h60
Drill Guide:
  text ".Layer_Name" at 233.22,-976.6 h60
M1 Board Outline:
  the board outline again, w10
  text ".Layer_Name" at 233.22,-976.6 h60
M2 Board Dimensions:
  rectangle: -343.78,-393.11 -218.78,-268.11
  rectangle: -218.78,-518.11 156.22,-393.11
  lines w7: -343.78,-393.11 656.22,-393.11 ; -218.78,-518.11 -218.78,-268.11 ; -93.78,-518.11 -93.78,-268.11 ; 156.22,-518.11 156.22,-268.11 ; 406.22,-518.11 406.22,-268.11 ; -343.78,-518.11 656.22,-518.11 656.22,-268.11 -343.78,-268.11 -343.78,-518.11
  text ".Layer_Name" at 233.22,-976.6 h60
M3 3D STEP Top:
  text ".Layer_Name" at 233.22,-976.6 h60
M4 3D STEP Bottom:
  text ".Layer_Name" at 233.22,-976.6 h60
M5 Assembly Top:
  lines w10: -635.78,-1048.28 5964.22,-1048.28 ; -635.78,-844.94 5966.22,-844.94 ; -635.78,-641.61 -635.78,-1251.61 3369.22,-1251.61 5966.22,-1251.61 5966.22,-641.61 -635.28,-641.61 -635.28,-1251.61 940.22,-1251.61 ; 1829.22,-1251.61 1829.22,-641.61 ; 3096.22,-844.94 3096.22,-641.61 ; 3936.22,-844.94 3936.22,-641.61 ; 4558.22,-1258.11 4558.22,-1055.28
  text "COMPONENTS MARKED 'DNP' SHOULD NOT BE POPULATED." at 809.72,-436.61 h60
  text "ASSEMBLY VARIANT:" at 809.22,-552.11 h60
  text ".VariantName" at 1845.22,-552.11 h60
  text "PCB VIEWED FROM TOP SIDE" at -572.28,-773.78 h60
  text "BOARD #:" at 1904.22,-773.78 h60
  text ".PRJ_Number" at 2449.72,-773.78 h60
  text "REV:" at 3294.22,-773.78 h60
  text ".PCB_Rev" at 3585.72,-773.78 h60
  text "SVN REV:" at 4132.22,-773.78 h60
  text ".VersionControl_RevNumber" at 4638.22,-773.78 h60
  text "TID #:" at 1904.22,-977.11 h60
  text ".TID" at 2449.72,-977.11 h60
  text "PLOT NAME =" at -572.28,-1182.45 h60
  text ".plot_File_Name" at 233.22,-1182.45 h60
  text "GENERATED    :" at 1906.22,-1182.45 h60
  text ".Print_Date" at 2775.72,-1182.45 h60
  text ".Print_Time" at 3504.72,-1182.45 h60
  text "TEXAS INSTRUMENTS" at 4769.22,-1182.45 h60
M6 Assembly Bottom:
  lines w10: -636.28,-845.44 5965.72,-845.44 ; -634.28,-1048.78 5965.72,-1048.78 ; 771.72,-1258.61 771.72,-1055.78 ; 1393.72,-845.44 1393.72,-642.11 ; 2233.72,-845.44 2233.72,-642.11 ; 3500.72,-1252.11 3500.72,-642.11 ; 4389.72,-1252.11 5965.22,-1252.11 5965.22,-642.11 -636.28,-642.11 -636.28,-1252.11 1960.72,-1252.11 5965.72,-1252.11 5965.72,-642.11
  text "COMPONENTS MARKED 'DNP' SHOULD NOT BE POPULATED." at 5758.22,-436.11 h60
  text ".VariantName" at 4714.22,-552.11 h60
  text "ASSEMBLY VARIANT:" at 5753.22,-552.11 h60
  text ".VersionControl_RevNumber" at 691.72,-774.28 h60
  text "SVN REV:" at 1197.72,-774.28 h60
  text ".PCB_Rev" at 1744.22,-774.28 h60
  text "REV:" at 2035.72,-774.28 h60
  text ".PRJ_Number" at 2880.22,-774.28 h60
  text "BOARD #:" at 3425.72,-774.28 h60
  text "PCB VIEWED FROM BOTTOM SIDE" at 5902.22,-774.28 h60
  text ".TID" at 2880.22,-977.61 h60
  text "TID #:" at 3425.72,-977.61 h60
  text "TEXAS INSTRUMENTS" at 560.72,-1182.95 h60
  text ".Print_Time" at 1825.22,-1182.95 h60
  text ".Print_Date" at 2554.22,-1182.95 h60
  text "GENERATED    :" at 3423.72,-1182.95 h60
  text ".plot_File_Name" at 5096.72,-1182.95 h60
  text "PLOT NAME =" at 5902.22,-1182.95 h60
M9 Title Sheet:
  drawing of 57 lines, arcs and shapes, not listed
  text "1" at 396.06,7918.39 h70
  text "2" at 2891.72,7918.39 h70
  text "3" at 5381.06,7918.39 h70
  text "4" at 7887.73,7918.39 h70
  text "5" at 10386.72,7918.39 h70
  text "6" at 12891.72,7918.39 h70
  text "A" at -760.28,6775.39 h70
  text "A" at 14039.72,6775.39 h70
  text "B" at -760.28,4395.39 h70
  text "B" at 14039.72,4395.39 h70
  text "C" at -760.28,2020.39 h70
  text "C" at 14039.72,2020.39 h70
  text "PROJECT TITLE:" at 10999.72,159.39 h45
  text ".PRJ_Title" at 11049.72,26.06 h70
  text "DESIGNED FOR:" at 10999.72,-141.61 h45
  text ".PRJ_Customer" at 11049.72,-281.61 h70
  text "D" at -760.28,-349.61 h70
  text "D" at 14039.72,-349.61 h70
  text "FILE NAME:" at 10999.72,-441.61 h45
  text ".PCB_File_Name_No_Path" at 11049.72,-561.61 h70
  text "Texas Instruments (TI) and/or its licensors do not warrant the accuracy or completeness of this specification" at 6030.22,-723.45 h45
  text "ENGINEER:" at 10999.72,-731.61 h45
  text "LAYOUT BY:" at 12504.72,-731.61 h45
  text "or any information contained therein. TI and/or its licensors do not warrant that this design will meet" at 5985.23,-836.11 h45
  text ".PRJ_Engineer" at 11049.72,-886.6 h70
  text ".PCB_Layout" at 12555.22,-886.6 h70
  text "the specifications, will be suitable for your application or fit for any particular purpose, or will operate in" at 5985.23,-948.78 h45
  text ".Layer_Name" at 233.22,-976.6 h60
  text "ALTIUM DESIGNER VERSION:" at 12504.72,-1041.61 h45
  text "an implementation. TI and/or its licensors do not warrant that the design is production worthy. You should" at 5985.23,-1061.44 h45
  text "completely validate and test your design implementation to confirm the system functionality for your application." at 6030.22,-1174.11 h45
  text ".print_Scale" at 11049.72,-1174.94 h70
  text ".Application_BuildNumber" at 12555.22,-1174.94 h70
  text "1" at 396.06,-1381.61 h70
  text "2" at 2891.72,-1381.61 h70
  text "3" at 5381.06,-1381.61 h70
  text "4" at 7887.73,-1381.61 h70
  text "5" at 10386.72,-1381.61 h70
  text "6" at 12891.72,-1381.61 h70
M10 Fab Notes:
  drawing of 189 lines, arcs and shapes, not listed
  text "DESIGN INFORMATION" at 12038.24,6238.06 h60
  text "MIN. TRACK WIDTH:" at 11393.68,6105.94 h60
  text "8" at 12489.92,6105.94 h60
  text "MIL" at 12644.68,6105.94 h60
  text "7.874" at 12323.54,5984.25 h60
  text "MIN. CLEARANCE:" at 11393.68,5981.81 h60
  text "MIL" at 12644.68,5981.81 h60
  text "MIN. VIA PAD SIZE:" at 11393.68,5857.69 h60
  text "24" at 12459.93,5857.69 h60
  text "MIL" at 12644.68,5857.69 h60
  text "0.05mm (2MIL)" at 12088.68,5727.79 h60
  text "MINIMUM ANNULAR RING" at 11064.45,5719.56 h60
  text "EXTERNAL" at 12796.68,5719.56 h60
  text "PER" at 11264.45,5609.44 h60
  text "IPC-D-275 CLASS 2 LEVEL C" at 11484.45,5609.43 h60
  text "MIL, HOLES" at 12972.68,5508.96 h60
  text "+/-" at 12580.22,5500.37 h60
  text "+/-" at 13434.22,5500.37 h60
  text "REGISTRATION TOLERANCES:" at 11064.45,5499.31 h60
  text "METAL" at 12264.22,5499.31 h60
  text "5" at 12840.42,5499.31 h60
  text "3" at 13673.42,5499.31 h60
  text "MIL" at 13789.68,5499.31 h60
  text "HOLE SIZE TOLERANCE (UNLESS OTHERWISE SPECIFIED):" at 11064.45,5400.99 h60
  text "+/-" at 13434.22,5398.12 h60
  text "3" at 13673.42,5397.06 h60
  text "MIL" at 13789.68,5397.06 h60
  text "MATERIAL:" at 10989.68,5259.41 h60
  text "FR-4 High Tg" at 11976.12,5130.89 h60
  text "X" at 11831.68,5122.9 h60
  text "FR-408" at 11410.68,5118.38 h60
  text "OTHER" at 12898.68,5118.38 h60
  text "62 MIL (1.6mm) +/-10%" at 11730.78,4975.35 h60
  text "X" at 11610.68,4972.9 h60
  text "THICKNESS:" at 11064.45,4967.13 h60
  text "OTHER" at 13015.68,4967.13 h60
  text "TOLERANCE:" at 11064.45,4828.81 h60
  text "X" at 11912.68,4828.81 h60
  text "ANSI IPC-6012 TYPE 3 CLASS 2" at 12090.7,4828.81 h60
  text "OTHER +/-" at 12090.68,4684.62 h60
  text "BOW & TWIST:" at 11064.45,4539.43 h60
  text "X" at 11912.68,4539.43 h60
  text "ANSI IPC-6012 TYPE 3 CLASS 2" at 12090.7,4539.43 h60
  text "OTHER +/-" at 12090.68,4392.74 h60
  text "DRILLING:" at 10989.68,4262.12 h60
  text "NC_DRILL FILES" at 12750.68,4156.93 h60
  text "REFERENCE:" at 11064.45,4152.99 h60
  text "X" at 11721.68,4152.9 h60
  text "AS SHOWN" at 11899.68,4152.99 h60
  text "X" at 12622.68,4152.99 h60
  text "OTHER" at 13048.68,4010.74 h60
  text "PTH COPPER THICKNESS:" at 11064.13,4007.21 h60
  text "X" at 12203.36,4007.21 h60
  text "20-30 um" at 12331.36,4007.21 h60
  text "BOARD FINISH:" at 10989.68,3859.62 h60
  text "SILKSCREEN:" at 11144.9,3749.49 h60
  text "X" at 12102.68,3749.49 h60
  text "TOP" at 12219.68,3749.49 h60
  text "X" at 12612.68,3749.49 h60
  text "BOTTOM" at 12730.68,3749.49 h60
  text "SILKSCREEN COLOR:" at 11144.9,3594.3 h60
  text "X" at 12101.68,3594.3 h60
  text "WHITE" at 12219.68,3594.3 h60
  text "OTHER" at 12730.68,3594.3 h60
  text "X" at 12232.68,3450.85 h60
  text "GREEN" at 12350.68,3450.85 h60
  text "OTHER" at 12968.68,3450.85 h60
  text "SOLDER RESIST COLOR:" at 11144.9,3443.99 h60
  text "X" at 12232.68,3296.6 h60
  text "MATTE" at 12350.68,3296.6 h60
  text "SEMI-GLOSS" at 12968.22,3295.96 h60
  text "IMMERSION GOLD (ENIG)" at 12050.68,3123.83 h60
  text "ENEPIG" at 13388.22,3116.61 h60
  text "SURFACE FINISH:" at 10989.68,3115.61 h60
  text "X" at 11872.68,3115.61 h60
  text "IMM. TIN/SILVER OR EQUIV" at 11319.22,2978.29 h60
  text "OTHER" at 12750.68,2974.36 h60
  text "ARRAY/PANEL:" at 10989.68,2818.98 h60
  text "CUT AND TRIM PER M1 BOARD OUTLINE" at 12050.68,2810.76 h60
  text "N.C. ROUTE" at 12050.68,2674.79 h60
  text "X" at 12738.68,2674.79 h60
  text "V. SCORE" at 12916.68,2674.79 h60
  text "CERTIFICATION:" at 10989.68,2545.66 h60
  text "MATERIALS AND WORKMANSHIP FOR ALL PCBS" at 11714.68,2545.66 h60
  text "TO MEET OR EXCEED THE REQUIREMENTS OF:" at 11714.68,2451.6 h60
  text "X" at 11352.19,2322.97 h60
  text "ANSI IPC-A-600F CLASS ->" at 11480.18,2322.97 h60
  text "X" at 13128.19,2322.97 h60
  text "2" at 13238.18,2322.97 h60
  text "1" at 12923.18,2321.47 h60
  text "3" at 13592.18,2321.47 h60
  text "X" at 12164.19,2175.28 h60
  text "RoHS" at 12292.18,2175.28 h60
  text "OTHER" at 12936.58,2175.28 h60
  text "PER ORDER" at 13333.64,2175.28 h60
  text "ALL BOARDS MUST MEET OR EXCEED UL94-V0 REQUIREMENTS." at 11017.22,2021.46 h60
  text "PCB MUST BEAR THE UL94V-0 UL REGISTERED MATERIAL ID NUMBER" at 11017.22,1905.39 h60
  text "ADDITIONAL REQUIREMENTS:" at 10989.68,1735.97 h60
  text "MICROSECTION:" at 11064.45,1628.84 h60
  text "YES" at 11970.18,1628.84 h60
  text "REQUIRED" at 12831.68,1484.51 h60
  text "BARE BOARD ELEC. TEST:" at 11064.45,1481.65 h60
  text "NONE" at 12370.18,1481.65 h60
  text "X" at 12713.68,1481.65 h60
  text "PER ORDER" at 13423.68,1481.65 h60
  text "XX MIL VIAS REQUIRE NON-CONDUCTIVE FILL AND PLANARIZE" at 11232.6,1276.71 h59
  text "XX MIL VIAS REQUIRE CONDUCTIVE FILL AND PLANARIZE" at 11240.6,1172.73 h60
  text "OUTER XX MIL TRACES REQUIRE 50 OHM SINGLE-ENDED IMPEDANCE" at 11239.61,1009.35 h58
  text "LAYER 2 & 3 (INNER LAYERS) XX MIL WIDE, XX MIL SPACE / TRACES REQUIRE 100 OHM DIFFERENTIAL IMPEDANCE" at 11231.61,773.63 h60
  text ".Layer_Name" at 233.22,-976.6 h60
M11 Gerber Information:
  lines w10: -635.78,-1048.28 5964.22,-1048.28 ; -635.78,-844.94 5966.22,-844.94 ; -635.78,-641.61 -635.78,-1251.61 3369.22,-1251.61 5966.22,-1251.61 5966.22,-641.61 -635.28,-641.61 -635.28,-1251.61 940.22,-1251.61 ; 1829.22,-1251.61 1829.22,-641.61 ; 3096.22,-844.94 3096.22,-641.61 ; 3936.22,-844.94 3936.22,-641.61 ; 4558.22,-1258.11 4558.22,-1055.28
  text "ALL ARTWORK VIEWED FROM TOP SIDE" at -572.28,-773.78 h60
  text "BOARD #:" at 1904.22,-773.78 h60
  text ".PRJ_Number" at 2449.72,-773.78 h60
  text "REV:" at 3294.22,-773.78 h60
  text ".PCB_Rev" at 3585.72,-773.78 h60
  text "SVN REV:" at 4132.22,-773.78 h60
  text ".VersionControl_RevNumber" at 4638.22,-773.78 h60
  text "LAYER NAME =" at -572.28,-976.6 h60
  text "TID #:" at 1904.22,-977.11 h60
  text ".TID" at 2449.72,-977.11 h60
  text "PLOT NAME =" at -572.28,-1182.45 h60
  text ".plot_File_Name" at 233.22,-1182.45 h60
  text "GENERATED    :" at 1906.22,-1182.45 h60
  text ".Print_Date" at 2775.72,-1182.45 h60
  text ".Print_Time" at 3504.72,-1182.45 h60
  text "TEXAS INSTRUMENTS" at 4769.22,-1182.45 h60
M12 Stackup:
  drawing of 191 lines, arcs and shapes, not listed
  text "Layer" at 9467.81,7261.83 h60
  text "Name" at 9877.73,7261.83 h60
  text "Material" at 10807.47,7261.83 h60
  text "Thickness" at 11667.24,7261.83 h60
  text "Constant" at 12317.07,7261.83 h60
  text "Board Layer Stack" at 12886.94,7261.83 h60
  text "1" at 9467.81,7141.83 h60
  text "Top Overlay" at 9877.73,7141.83 h60
  text "2" at 9467.81,7021.83 h60
  text "Top Solder" at 9877.73,7021.83 h60
  text "Solder Resist" at 10807.47,7021.83 h60
  text "0.40mil" at 11667.24,7021.83 h60
  text "3.5" at 12317.07,7021.83 h60
  text "3" at 9467.81,6901.83 h60
  text "Top Layer" at 9877.73,6901.83 h60
  text "Copper" at 10807.47,6901.83 h60
  text "1.40mil" at 11667.24,6901.83 h60
  text "4" at 9467.81,6781.83 h60
  text "Dielectric1" at 9877.73,6781.83 h60
  text "FR-4 High Tg" at 10807.47,6781.83 h60
  text "59.20mil" at 11667.24,6781.83 h60
  text "4.8" at 12317.07,6781.83 h60
  text "5" at 9467.81,6661.83 h60
  text "Bottom Layer" at 9877.73,6661.83 h60
  text "Copper" at 10807.47,6661.83 h60
  text "1.40mil" at 11667.24,6661.83 h60
  text "6" at 9467.81,6541.83 h60
  text "Bottom Solder" at 9877.73,6541.83 h60
  text "Solder Resist" at 10807.47,6541.83 h60
  text "0.40mil" at 11667.24,6541.83 h60
  text "3.5" at 12317.07,6541.83 h60
  text "7" at 9467.81,6421.83 h60
  text "Bottom Overlay" at 9877.73,6421.83 h60
  text ".Layer_Name" at 233.22,-976.6 h60
M13 Component Bodies Top:
  text ".Layer_Name" at 233.22,-976.6 h60
M14 Component Bodies Bottom:
  text ".Layer_Name" at 233.22,-976.6 h60
M15 Courtyards Top:
  text ".Layer_Name" at 233.22,-976.6 h60
M16 Courtyards Bottom:
  text ".Layer_Name" at 233.22,-976.6 h60
Drill Drawing:
  circle w10: c5020.02,3055.05 r27.66
  lines w10: 4992.36,2778.48 5047.68,2778.48 5047.68,2833.79 4992.36,2833.79 4992.36,2778.48 ; 4992.36,2958.25 5047.68,2958.25 5020.02,2902.93 4992.36,2958.25 ; 4992.36,3165.68 5006.19,3165.68 5006.19,3151.85 5033.85,3151.85 5033.85,3165.68 5047.68,3165.68 5047.68,3193.34 5033.85,3193.34 5033.85,3207.17 5006.19,3207.17 5006.19,3193.34 4992.36,3193.34 4992.36,3165.68 ; 4992.36,3290.14 5006.19,3290.14 5020.02,3276.31 5033.85,3290.14 5047.68,3290.14 5033.85,3303.97 5047.68,3317.8 5033.85,3317.8 5020.02,3331.62 5006.19,3317.8 4992.36,3317.8 5006.19,3303.97 4992.36,3290.14
  lines w12: 4942.22,2741.14 8174.98,2741.14 ; 4942.22,3363.43 8174.98,3363.43 ; 5280.39,2616.68 5280.39,3487.89 ; 5612.5,2616.68 5612.5,3487.89 ; 6249.51,2616.68 6249.51,3487.89 ; 6508.86,2616.68 6508.86,3487.89 ; 6884.28,2616.68 6884.28,3487.89 ; 7608.13,2616.68 7608.13,3487.89 ; 4942.22,2616.68 8174.98,2616.68 8174.98,3487.89 4942.22,3487.89 4942.22,2616.68
  text "Symbol" at 5016.9,3400.77 h72
  text "Quantity" at 5317.73,3400.77 h72
  text "Finished Hole Size" at 5649.84,3400.77 h72
  text "Plated" at 6286.84,3400.77 h72
  text "Hole Type" at 6546.2,3400.77 h72
  text "Drill Layer Pair" at 6921.62,3400.77 h72
  text "Hole Tolerance" at 7645.47,3400.77 h72
  text "6" at 5317.73,3276.31 h60
  text "7.87mil (0.200mm)" at 5649.84,3276.31 h60
  text "PTH" at 6286.84,3276.31 h60
  text "Round" at 6546.2,3276.31 h60
  text "Top Layer - Bottom Layer" at 6921.62,3276.31 h60
  text "18" at 5317.73,3151.85 h60
  text "10.00mil (0.254mm)" at 5649.84,3151.85 h60
  text "PTH" at 6286.84,3151.85 h60
  text "Round" at 6546.2,3151.85 h60
  text "Top Layer - Bottom Layer" at 6921.62,3151.85 h60
  text "12" at 5317.73,3027.39 h60
  text "39.37mil (1.000mm)" at 5649.84,3027.39 h60
  text "PTH" at 6286.84,3027.39 h60
  text "Round" at 6546.2,3027.39 h60
  text "Top Layer - Bottom Layer" at 6921.62,3027.39 h60
  text "1" at 5317.73,2902.93 h60
  text "40.00mil (1.016mm)" at 5649.84,2902.93 h60
  text "PTH" at 6286.84,2902.93 h60
  text "Round" at 6546.2,2902.93 h60
  text "Top Layer - Bottom Layer" at 6921.62,2902.93 h60
  text "15" at 5317.73,2778.48 h60
  text "47.24mil (1.200mm)" at 5649.84,2778.48 h60
  text "PTH" at 6286.84,2778.48 h60
  text "Round" at 6546.2,2778.48 h60
  text "Top Layer - Bottom Layer" at 6921.62,2778.48 h60
  text "52 Total" at 5317.73,2654.02 h60
  text ".Layer_Name" at 233.22,-976.6 h60
M17 Embedded Cavity:
  text ".Layer_Name" at 233.22,-976.6 h60
M18 Embedded Assembly:
  text ".Layer_Name" at 233.22,-976.6 h60
M19 Embedded Keepout:
  text ".Layer_Name" at 233.22,-976.6 h60

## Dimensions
0,0 to 2165.35,0 on M2 Board Dimensions
0,0 to 0,1771.65 on M2 Board Dimensions
-343.78,-518.11 to 656.22,-518.11 on M2 Board Dimensions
